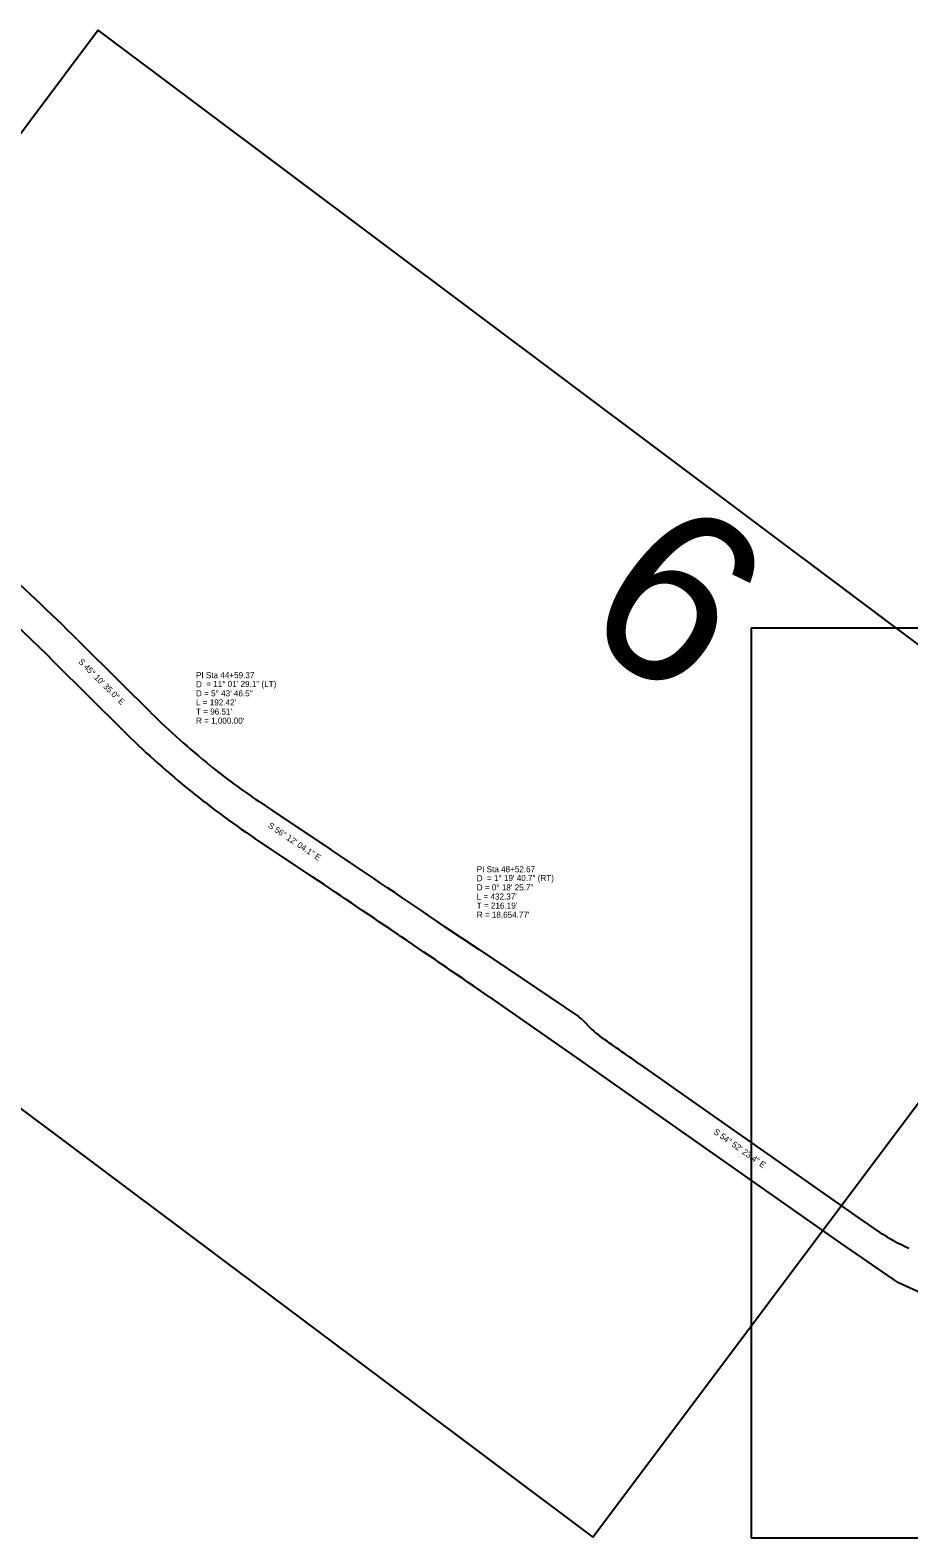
# Model space of a CAD drawing. Extents: x 925297 to 940193, y 663541 to 689899.
# Drawn here: x 930888 to 931902, y 684208 to 685948 of the extents above; entities that cross this region are included whole.
import ezdxf

# ---------------------------------------------------------------- set-up
doc = ezdxf.new("R2010")
doc.units = 0
for name, color, linetype in [('Default', 7, 'Continuous'), ('Exist Horizontal Alignment Curve and Spiral Data', 7, 'Continuous'), ('Exist Horizontal Alignment Direction Label', 7, 'Continuous'), ('Prop DSN Text', 7, 'Continuous'), ('Prop Shade Light', 7, 'Continuous'), ('Sheet Layout Plan Border', 7, 'Continuous')]:
    doc.layers.add(name, color=color, linetype=linetype)

msp = doc.modelspace()

# ---------------------------------------------------------------- linework, layer by layer
at = {"layer": 'Default'}
for p, q in [((930966.1, 685948.1), (930336.5, 685107.8)), ((932166.5, 685048.6), (930966.1, 685948.1)), ((933219.8, 685257.7), (931719.8, 685257.7)), ((931719.8, 685257.7), (931719.8, 684207.7)), ((930336.5, 685107.8), (931536.9, 684208.3)), ((931536.9, 684208.3), (932166.5, 685048.6)), ((931719.8, 684207.7), (933219.8, 684207.7))]:
    msp.add_line(p, q, dxfattribs=at)
at = {"layer": 'Prop Shade Light'}
for p, q in [((930942.3, 685244.2), (930991.8, 685195)), ((930995.1, 685139.5), (930916.2, 685217.9)), ((930991.8, 685195), (931026.5, 685160.6)), ((931151.9, 685057.5), (931167.6, 685047)), ((931167.6, 685047), (931235.1, 685001.8)), ((931214, 684970.4), (931146.5, 685015.5)), ((931365.2, 684913.9), (931405.8, 684886.9)), ((931405.8, 684886.9), (931520.4, 684809.3)), ((931514.4, 684765), (931418.7, 684831.4)), ((931524.9, 684805.6), (931535.9, 684794.5)), ((931823.1, 684548), (931514.4, 684765)), ((931590.5, 684754.9), (931681.4, 684691)), ((931681.4, 684691), (931715.9, 684666.9)), ((931715.9, 684666.9), (931843.5, 684576.9)), ((931843.5, 684576.9), (931868.3, 684560.3)), ((931889.7, 684502.2), (931823.1, 684548)), ((931945.7, 684476.3), (931889.7, 684502.2))]:
    msp.add_line(p, q, dxfattribs=at)
for centre, radius, start, end in [((929149.5, 683440.3), 2506.2, 45.1764, 54.5284), ((929149.5, 683440.3), 2543.3, 45.1764, 51.2301), ((931713, 685861.8), 981.4, 225.6054, 230.9744), ((931713, 685861.8), 1018.4, 225.1764, 236.2011), ((931582.8, 685701.2), 774.6, 230.9744, 236.2011), ((920846.9, 669483.6), 18674.3, 55.71916, 56.20114), ((920846.9, 669483.6), 18636.4, 55.44041, 56.20114), ((931502.3, 684782.7), 32.2, 45.4748, 55.8717), ((931583.2, 684841.5), 66.7, 224.8003, 235.0437), ((920846.9, 669483.6), 18671.8, 54.87317, 55.04368), ((931977.4, 684722.6), 195.6, 236.097, 247.2391)]:
    msp.add_arc(centre, radius, start, end, dxfattribs=at)
at = {"layer": 'Sheet Layout Plan Border'}
msp.add_line((931719.8, 685257.6), (931719.8, 684207.7), dxfattribs=at)

# ---------------------------------------------------------------- texts
at = {"layer": 'Exist Horizontal Alignment Curve and Spiral Data'}
for s, p in [('PI Sta 44+59.37', (931079, 685200)), ('D', (931079, 685189.5)), ('D = 5%%d 43\' 46.5"', (931079, 685179)), ('= 11%%d 01\' 29.1" (LT)', (931090.8, 685189.9)), ("T = 96.51'", (931079, 685158)), ("L = 192.42'", (931079, 685168.5)), ("R = 1,000.00'", (931079, 685147.5)), ('PI Sta 48+52.67', (931403, 684976)), ('= 1%%d 19\' 40.7" (RT)', (931414.8, 684965.9)), ('D', (931403, 684965.5)), ('D = 0%%d 18\' 25.7"', (931403, 684955)), ("T = 216.19'", (931403, 684934)), ("L = 432.37'", (931403, 684944.5)), ("R = 18,654.77'", (931403, 684923.5))]:
    msp.add_text(s, height=7, dxfattribs=at).set_placement(p)
at = {"layer": 'Exist Horizontal Alignment Direction Label'}
for s, rotation, p in [('S 45%%d 10\' 35.0" E', 315.1764, (930942.6, 685218.3)), ('S 56%%d 12\' 04.1" E', 326.2011, (931161.4, 685028.3)), ('S 54%%d 52\' 23.4" E', 324.8732, (931675.6, 684674.8))]:
    msp.add_text(s, height=7, rotation=rotation, dxfattribs=at).set_placement(p)
at = {"layer": 'Prop DSN Text'}
msp.add_text('6', height=200, rotation=323.1572, dxfattribs=at).set_placement((931515.6, 685259.1))

doc.saveas('drawing.dxf')
